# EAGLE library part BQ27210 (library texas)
Li-Ion AND Li-Pol BATTERY GAS GAUGE IC FOR PORTABLE APPLICATIONS I2C Communication (bqJUNIOR) Source: www.ti.com .. bq27010.pdf
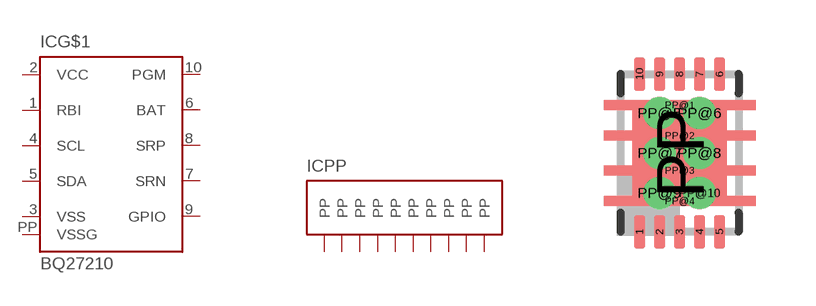
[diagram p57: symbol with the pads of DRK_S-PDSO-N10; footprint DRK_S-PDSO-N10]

Designator prefix IC; gates PP=PWR-PP10 G$1=BQ27210

## BQ27210 (MPN: BQ27210DRKR; OC_FARNELL: 1534540; OC_NEWARK: 30M3431)  [DRK_S-PDSO-N10]
1  G$1:RBI  in
2  G$1:VCC  in
3  G$1:VSS  in
4  G$1:SCL  in
5  G$1:SDA
6  G$1:BAT  in
7  G$1:SRN  in
8  G$1:SRP  in
9  G$1:GPIO
10  G$1:PGM  in
PP  G$1:VSSG  in
PP@1  PP:PP  pwr
PP@2  PP:PP  pwr
PP@3  PP:PP  pwr
PP@4  PP:PP  pwr
PP@5  PP:PP  pwr
PP@6  PP:PP  pwr
PP@7  PP:PP  pwr
PP@8  PP:PP  pwr
PP@9  PP:PP  pwr
PP@10  PP:PP  pwr

## Footprint DRK_S-PDSO-N10 (pad centres in mm)
DRK (S-PDSO-N10) Source: www.ti.com .. bq27010.pdf
smd 0.28 x 0.85: 1 -1,-1.975; 2 -0.5,-1.975; 3 0,-1.975; 4 0.5,-1.975; 5 1,-1.975; 6 1,1.975; 7 0.5,1.975; 8 0,1.975; 9 -0.5,1.975; 10 -1,1.975
smd 2.35 x 2.65: PP 0,0
smd 3.8 x 0.25: PP@1 0,1.2; PP@2 0,0.435; PP@3 0,-0.435; PP@4 0,-1.2
drill 0.3 pad 0.5 round: PP@5 -0.5,1; PP@6 0.5,1; PP@7 -0.5,0; PP@8 0.5,0; PP@9 -0.5,-1; PP@10 0.5,-1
